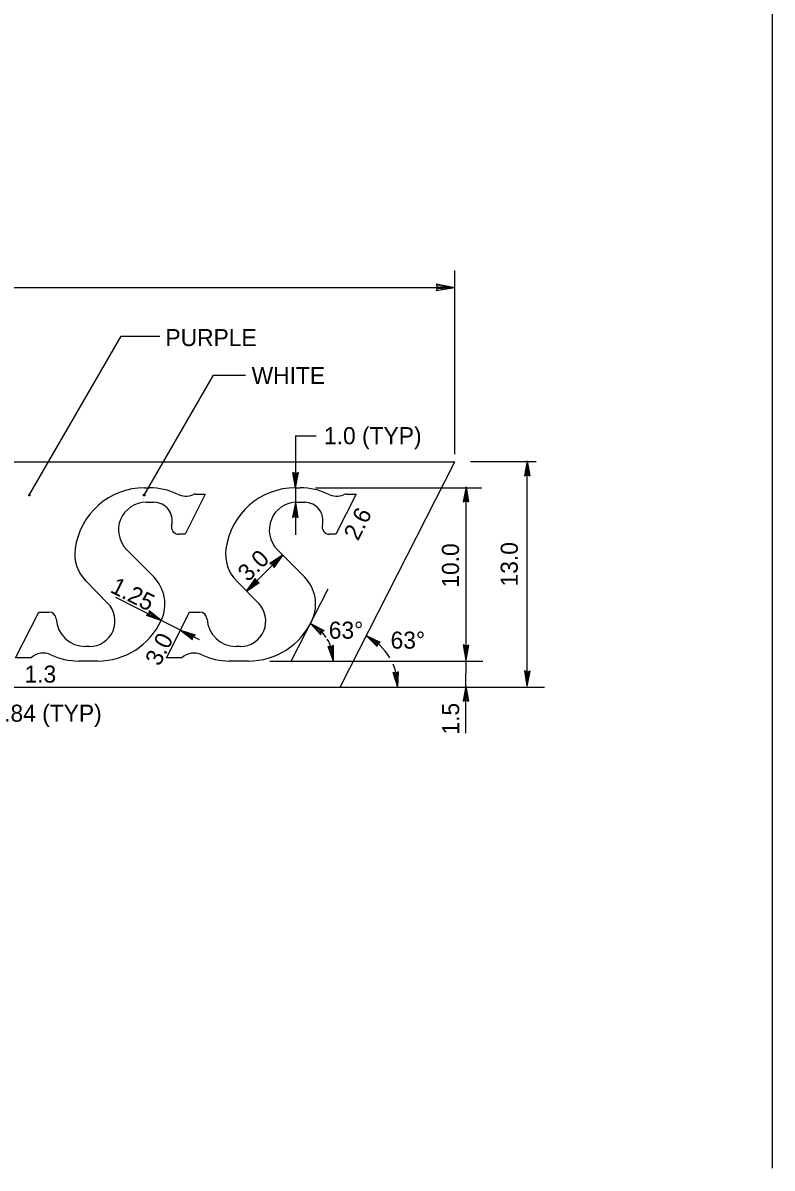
# Model space of a CAD drawing. Extents: x 10268197 to 10269179, y 2141503 to 2142677.
# Drawn here: x 10268630.99 to 10268661.74, y 2141959.11 to 2142006.15 of the extents above; entities that cross this region are included whole.
import ezdxf

# ---------------------------------------------------------------- set-up
doc = ezdxf.new("R2010")
doc.units = 0
for name, color, linetype in [('1', 7, 'Continuous'), ('20', 7, 'Continuous'), ('21', 7, 'Continuous'), ('NonPlottingEle_dp', 7, 'Continuous')]:
    doc.layers.add(name, color=color, linetype=linetype)

msp = doc.modelspace()

# ---------------------------------------------------------------- linework, layer by layer
at = {"layer": '1'}
for p, q in [((10268619.121, 2141988.121), (10268648.726, 2141988.121)), ((10268644.011, 2141978.867), (10268648.726, 2141988.121)), ((10268635.99, 2141987.054), (10268636.188, 2141987.054)), ((10268638.479, 2141986.791), (10268637.648, 2141985.146)), ((10268638.087, 2141986.791), (10268638.479, 2141986.791)), ((10268642.177, 2141987.054), (10268642.376, 2141987.054)), ((10268644.667, 2141986.791), (10268643.835, 2141985.146)), ((10268644.275, 2141986.791), (10268644.667, 2141986.791)), ((10268636.054, 2141986.456), (10268636.373, 2141986.456)), ((10268642.241, 2141986.456), (10268642.56, 2141986.456)), ((10268637.648, 2141985.146), (10268637.387, 2141985.146)), ((10268643.835, 2141985.146), (10268643.573, 2141985.146)), ((10268635.247, 2141984.518), (10268636.361, 2141983.396)), ((10268641.435, 2141984.518), (10268642.549, 2141983.396)), ((10268634.47, 2141982.317), (10268633.583, 2141983.211)), ((10268640.657, 2141982.317), (10268639.77, 2141983.212)), ((10268630.692, 2141980.066), (10268631.642, 2141981.946)), ((10268631.642, 2141981.946), (10268632.063, 2141981.947)), ((10268636.88, 2141980.066), (10268637.83, 2141981.947)), ((10268637.83, 2141981.947), (10268638.25, 2141981.946)), ((10268633.727, 2141980.533), (10268633.556, 2141980.533)), ((10268639.915, 2141980.533), (10268639.743, 2141980.533)), ((10268631.327, 2141980.066), (10268630.692, 2141980.066)), ((10268634.066, 2141979.934), (10268633.278, 2141979.935)), ((10268637.515, 2141980.066), (10268636.88, 2141980.066)), ((10268640.253, 2141979.934), (10268639.465, 2141979.935)), ((10268618.538, 2141978.866), (10268644.011, 2141978.867))]:
    msp.add_line(p, q, dxfattribs=at)
for centre, radius, start, end in [((10268636.054, 2141985.319), 1.137, 90, 224.7881), ((10268636.373, 2141985.708), 0.748, 345.4379, 90), ((10268642.241, 2141985.319), 1.137, 90, 224.7881), ((10268642.56, 2141985.708), 0.748, 345.4379, 90), ((10268637.386, 2141985.445), 0.299, 165.4379, 270), ((10268643.574, 2141985.445), 0.299, 165.4379, 270), ((10268633.727, 2141981.58), 1.047, 270, 44.7784), ((10268639.914, 2141981.58), 1.047, 270, 44.7784), ((10268632.063, 2141981.647), 0.299, 3.1643, 90), ((10268633.556, 2141981.73), 1.196, 183.1643, 270), ((10268638.25, 2141981.647), 0.299, 3.1643, 90), ((10268639.743, 2141981.73), 1.196, 183.1643, 270)]:
    msp.add_arc(centre, radius, start, end, dxfattribs=at)
for centre, major_axis, start_param, end_param in [((10268635.99, 2141984.154), (0, 2.9), 0, 1.436562), ((10268636.188, 2141984.417), (0, 2.637), 5.830963, 6.283185), ((10268637.675, 2141987.501), (0, 0.791), 2.68937, 3.526171), ((10268638.087, 2141986.474), (0, 0.316), 0, 0.384579), ((10268642.177, 2141984.154), (0, 2.9), 0, 1.436562), ((10268642.376, 2141984.417), (0, 2.637), 5.830963, 6.283185), ((10268643.862, 2141987.501), (0, 0.791), 2.68937, 3.526171), ((10268644.275, 2141986.474), (0, 0.316), 0, 0.384579), ((10268634.693, 2141984.33), (0, 1.582), 1.436562, 2.356194), ((10268640.88, 2141984.33), (0, 1.582), 1.436562, 2.356194), ((10268635.251, 2141982.277), (0, -1.582), 1.133591, 2.356194), ((10268641.438, 2141982.277), (0, -1.582), 1.133591, 2.356194), ((10268634.065, 2141982.835), (0, -2.9), 0, 1.133591), ((10268640.253, 2141982.835), (0, -2.9), 0, 1.133591), ((10268631.829, 2141979.528), (0, -0.738), 2.69443, 3.895387), ((10268633.278, 2141982.572), (0, -2.637), 5.836023, 6.283185), ((10268638.017, 2141979.528), (0, -0.738), 2.69443, 3.895387), ((10268639.465, 2141982.572), (0, -2.637), 5.836023, 6.283185)]:
    msp.add_ellipse(centre, major_axis=major_axis, ratio=0.992614, start_param=start_param, end_param=end_param, dxfattribs=at)
at = {"layer": '20'}
for p, q in [((10268648.726, 2141988.834), (10268648.726, 2141995.984)), ((10268648.726, 2141995.272), (10268601.689, 2141995.272)), ((10268631.256, 2141986.753), (10268635.028, 2141993.285)), ((10268635.028, 2141993.285), (10268636.616, 2141993.286)), ((10268635.973, 2141986.753), (10268638.815, 2141991.675)), ((10268638.815, 2141991.675), (10268640.133, 2141991.675)), ((10268642.177, 2141989.184), (10268642.178, 2141987.054)), ((10268642.177, 2141989.184), (10268643.035, 2141989.184)), ((10268648.726, 2141988.428), (10268648.726, 2141988.834)), ((10268652.056, 2141988.121), (10268649.364, 2141988.121)), ((10268651.694, 2141978.905), (10268651.694, 2141988.16)), ((10268642.178, 2141987.054), (10268642.178, 2141986.454)), ((10268643.005, 2141987.054), (10268649.83, 2141987.054)), ((10268649.179, 2141979.973), (10268649.179, 2141987.092)), ((10268642.178, 2141986.454), (10268642.177, 2141985.122)), ((10268640.166, 2141982.812), (10268641.659, 2141984.293)), ((10268636.673, 2141981.607), (10268634.814, 2141982.547)), ((10268642.008, 2141979.934), (10268643.517, 2141982.896)), ((10268637.458, 2141981.21), (10268636.673, 2141981.607)), ((10268638.243, 2141980.813), (10268637.458, 2141981.21)), ((10268641.125, 2141979.935), (10268644.555, 2141979.934)), ((10268644.555, 2141979.934), (10268649.868, 2141979.934)), ((10268649.178, 2141978.906), (10268649.179, 2141979.973)), ((10268644.011, 2141978.867), (10268652.397, 2141978.867)), ((10268649.178, 2141976.979), (10268649.178, 2141978.906))]:
    msp.add_line(p, q, dxfattribs=at)
for centre in [(10268631.257, 2141986.753), (10268635.973, 2141986.753)]:
    msp.add_circle(centre, 0.0356, dxfattribs=at)
for centre, radius, start, end in [((10268642.008, 2141979.935), 1.73, 33.9529, 63.0014), ((10268642.008, 2141979.935), 1.73, 0, 31.4593), ((10268644.011, 2141978.867), 2.37, 30.3328, 63.0012), ((10268644.011, 2141978.867), 2.37, 360, 23.4794)]:
    msp.add_arc(centre, radius, start, end, dxfattribs=at)
at = {"layer": '21'}
for p, q in [((10268648.009, 2141995.285), (10268647.947, 2141995.149)), ((10268648.726, 2141995.272), (10268647.947, 2141995.149)), ((10268648.726, 2141995.272), (10268647.951, 2141995.423)), ((10268647.951, 2141995.423), (10268648.009, 2141995.285)), ((10268648.726, 2141995.272), (10268647.98, 2141995.22)), ((10268648.726, 2141995.272), (10268647.981, 2141995.35)), ((10268651.694, 2141988.16), (10268651.574, 2141987.54)), ((10268651.694, 2141988.16), (10268651.632, 2141987.564)), ((10268651.694, 2141988.16), (10268651.793, 2141987.537)), ((10268651.694, 2141988.16), (10268651.736, 2141987.563)), ((10268642.178, 2141987.054), (10268642.078, 2141987.678)), ((10268642.187, 2141987.628), (10268642.078, 2141987.678)), ((10268642.178, 2141987.054), (10268642.136, 2141987.652)), ((10268642.178, 2141987.054), (10268642.298, 2141987.674)), ((10268642.178, 2141987.054), (10268642.24, 2141987.65)), ((10268642.298, 2141987.674), (10268642.187, 2141987.628)), ((10268651.574, 2141987.54), (10268651.684, 2141987.586)), ((10268651.684, 2141987.586), (10268651.793, 2141987.537)), ((10268649.179, 2141987.092), (10268649.058, 2141986.473)), ((10268649.179, 2141987.092), (10268649.116, 2141986.497)), ((10268649.179, 2141987.092), (10268649.277, 2141986.469)), ((10268649.179, 2141987.092), (10268649.22, 2141986.495)), ((10268642.178, 2141986.454), (10268642.057, 2141985.834)), ((10268642.178, 2141986.454), (10268642.115, 2141985.858)), ((10268642.178, 2141986.454), (10268642.276, 2141985.83)), ((10268642.178, 2141986.454), (10268642.219, 2141985.857)), ((10268649.058, 2141986.473), (10268649.169, 2141986.518)), ((10268649.169, 2141986.518), (10268649.277, 2141986.469)), ((10268642.057, 2141985.834), (10268642.167, 2141985.88)), ((10268642.167, 2141985.88), (10268642.276, 2141985.83)), ((10268641.659, 2141984.293), (10268641.134, 2141983.942)), ((10268641.134, 2141983.942), (10268641.244, 2141983.895)), ((10268641.659, 2141984.293), (10268641.192, 2141983.917)), ((10268641.244, 2141983.895), (10268641.286, 2141983.783)), ((10268641.659, 2141984.293), (10268641.265, 2141983.843)), ((10268641.659, 2141984.293), (10268641.286, 2141983.783)), ((10268640.166, 2141982.812), (10268640.54, 2141983.321)), ((10268640.166, 2141982.812), (10268640.561, 2141983.262)), ((10268640.166, 2141982.812), (10268640.633, 2141983.187)), ((10268640.166, 2141982.812), (10268640.691, 2141983.163)), ((10268640.581, 2141983.209), (10268640.54, 2141983.321)), ((10268640.691, 2141983.163), (10268640.581, 2141983.209)), ((10268636.174, 2141981.994), (10268636.165, 2141981.875)), ((10268636.673, 2141981.607), (10268636.174, 2141981.994)), ((10268636.165, 2141981.875), (10268636.072, 2141981.8)), ((10268636.673, 2141981.607), (10268636.072, 2141981.8)), ((10268636.673, 2141981.607), (10268636.121, 2141981.839)), ((10268636.673, 2141981.607), (10268636.169, 2141981.931)), ((10268637.458, 2141981.21), (10268638.059, 2141981.017)), ((10268637.458, 2141981.21), (10268637.957, 2141980.823)), ((10268637.458, 2141981.21), (10268637.962, 2141980.885)), ((10268637.458, 2141981.21), (10268638.01, 2141980.978)), ((10268642.794, 2141981.477), (10268643.355, 2141981.189)), ((10268642.794, 2141981.477), (10268643.222, 2141981.014)), ((10268642.794, 2141981.477), (10268643.238, 2141981.075)), ((10268642.794, 2141981.477), (10268643.3, 2141981.158)), ((10268643.222, 2141981.014), (10268643.251, 2141981.13)), ((10268643.251, 2141981.13), (10268643.355, 2141981.189)), ((10268637.957, 2141980.823), (10268637.966, 2141980.942)), ((10268637.966, 2141980.942), (10268638.059, 2141981.017)), ((10268643.737, 2141980.568), (10268643.637, 2141980.502)), ((10268643.739, 2141979.937), (10268643.737, 2141980.568)), ((10268645.087, 2141980.979), (10268645.662, 2141980.717)), ((10268645.087, 2141980.979), (10268645.538, 2141980.536)), ((10268645.087, 2141980.979), (10268645.55, 2141980.598)), ((10268645.087, 2141980.979), (10268645.608, 2141980.684)), ((10268645.538, 2141980.536), (10268645.561, 2141980.654)), ((10268645.561, 2141980.654), (10268645.662, 2141980.717)), ((10268649.179, 2141979.973), (10268649.08, 2141980.597)), ((10268649.189, 2141980.547), (10268649.08, 2141980.597)), ((10268649.179, 2141979.973), (10268649.137, 2141980.57)), ((10268649.179, 2141979.973), (10268649.299, 2141980.593)), ((10268649.179, 2141979.973), (10268649.241, 2141980.568)), ((10268649.299, 2141980.593), (10268649.189, 2141980.547)), ((10268643.739, 2141979.937), (10268643.521, 2141980.529)), ((10268643.637, 2141980.502), (10268643.521, 2141980.529)), ((10268643.739, 2141979.937), (10268643.582, 2141980.514)), ((10268643.739, 2141979.937), (10268643.684, 2141980.533)), ((10268646.383, 2141978.864), (10268646.188, 2141979.465)), ((10268646.303, 2141979.433), (10268646.188, 2141979.465)), ((10268646.383, 2141978.864), (10268646.249, 2141979.447)), ((10268646.405, 2141979.495), (10268646.303, 2141979.433)), ((10268646.383, 2141978.864), (10268646.352, 2141979.462)), ((10268646.383, 2141978.864), (10268646.405, 2141979.495)), ((10268651.694, 2141978.905), (10268651.595, 2141979.529)), ((10268651.704, 2141979.479), (10268651.595, 2141979.529)), ((10268651.694, 2141978.905), (10268651.652, 2141979.502)), ((10268651.694, 2141978.905), (10268651.814, 2141979.525)), ((10268651.694, 2141978.905), (10268651.756, 2141979.501)), ((10268651.814, 2141979.525), (10268651.704, 2141979.479)), ((10268649.178, 2141978.906), (10268649.058, 2141978.286)), ((10268649.178, 2141978.906), (10268649.116, 2141978.309)), ((10268649.178, 2141978.906), (10268649.277, 2141978.282)), ((10268649.178, 2141978.906), (10268649.22, 2141978.308)), ((10268649.058, 2141978.286), (10268649.169, 2141978.331)), ((10268649.169, 2141978.331), (10268649.277, 2141978.282))]:
    msp.add_line(p, q, dxfattribs=at)
at = {"layer": 'NonPlottingEle_dp'}
msp.add_line((10268661.739, 2142055.108), (10268661.739, 2141959.108), dxfattribs=at)

# ---------------------------------------------------------------- texts
at = {"layer": '20'}
for s, p in [('PURPLE', (10268636.843, 2141992.873)), ('WHITE', (10268640.38, 2141991.315)), ('1.0 (TYP)', (10268643.349, 2141988.844)), ('63°', (10268643.546, 2141980.854)), ('63°', (10268646.083, 2141980.445)), ('1.3', (10268631.058, 2141979.05)), ('.84 (TYP)', (10268630.223, 2141977.443))]:
    msp.add_text(s, height=0.7, dxfattribs=at).set_placement(p)
for s, rotation, p in [('2.6', 63.1678, (10268644.747, 2141984.841)), ('3.0', 44.7737, (10268640.233, 2141983.157)), ('10.0', 90, (10268648.891, 2141982.95)), ('13.0', 90, (10268651.302, 2141983)), ('1.25', 333.1861, (10268634.533, 2141982.785)), ('3.0', 63.1839, (10268636.6, 2141979.69)), ('1.5', 90, (10268648.899, 2141976.915))]:
    msp.add_text(s, height=0.7, rotation=rotation, dxfattribs=at).set_placement(p)

doc.saveas('drawing.dxf')
